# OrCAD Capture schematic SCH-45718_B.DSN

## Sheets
1 Title, ToC and Rev History: title: FRDM-XS2410EVB; rev: B; note: SCH45718 - SPF45718
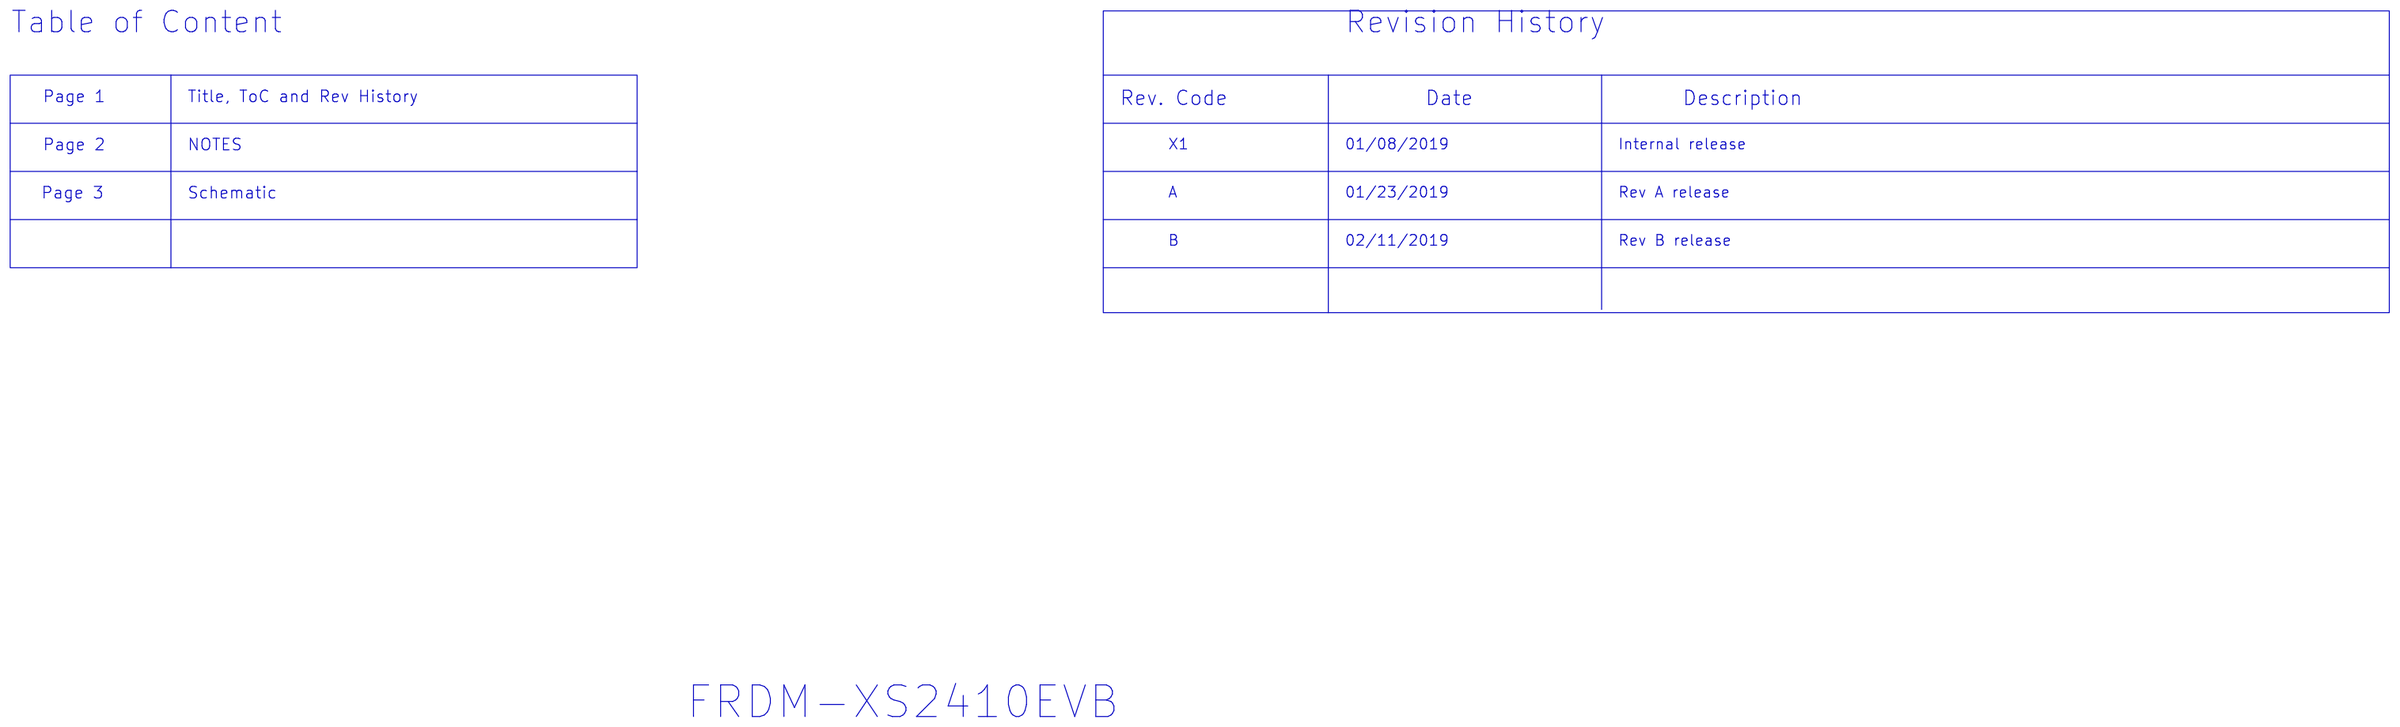
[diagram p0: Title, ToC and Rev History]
2 Notes
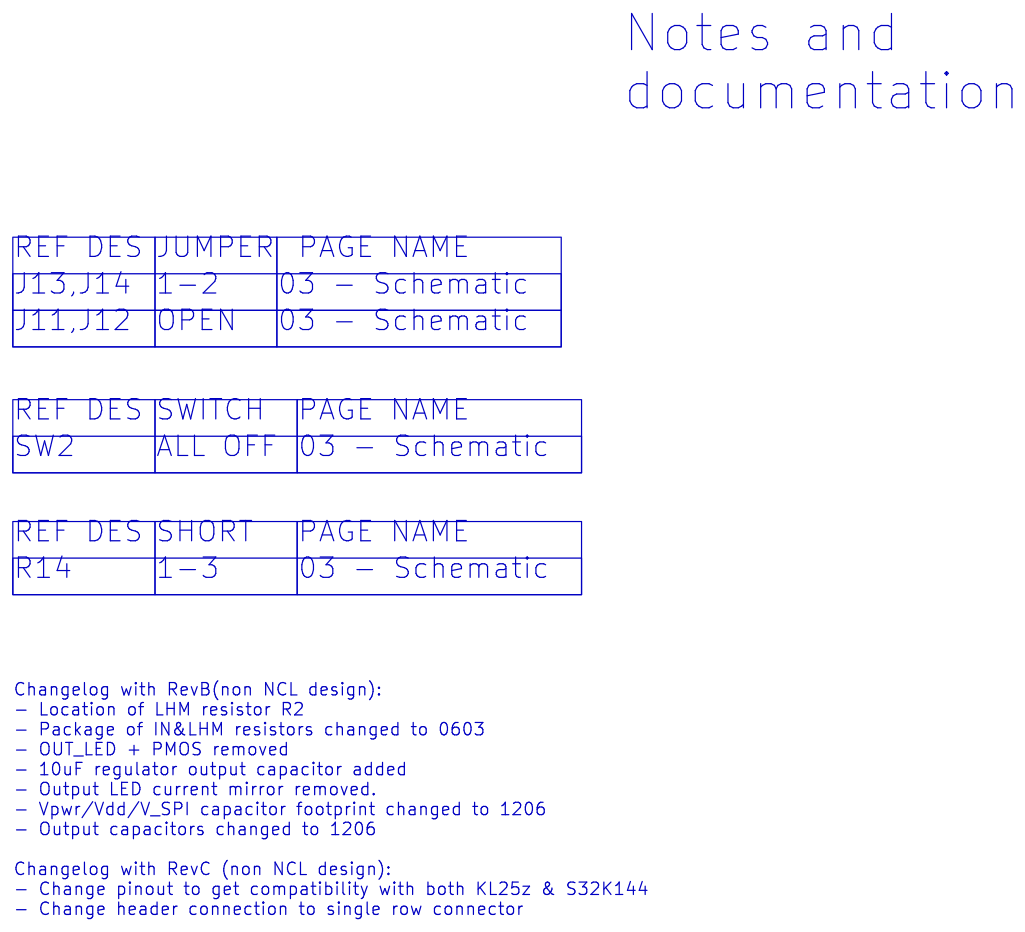
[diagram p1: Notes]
3 Schematic: size C
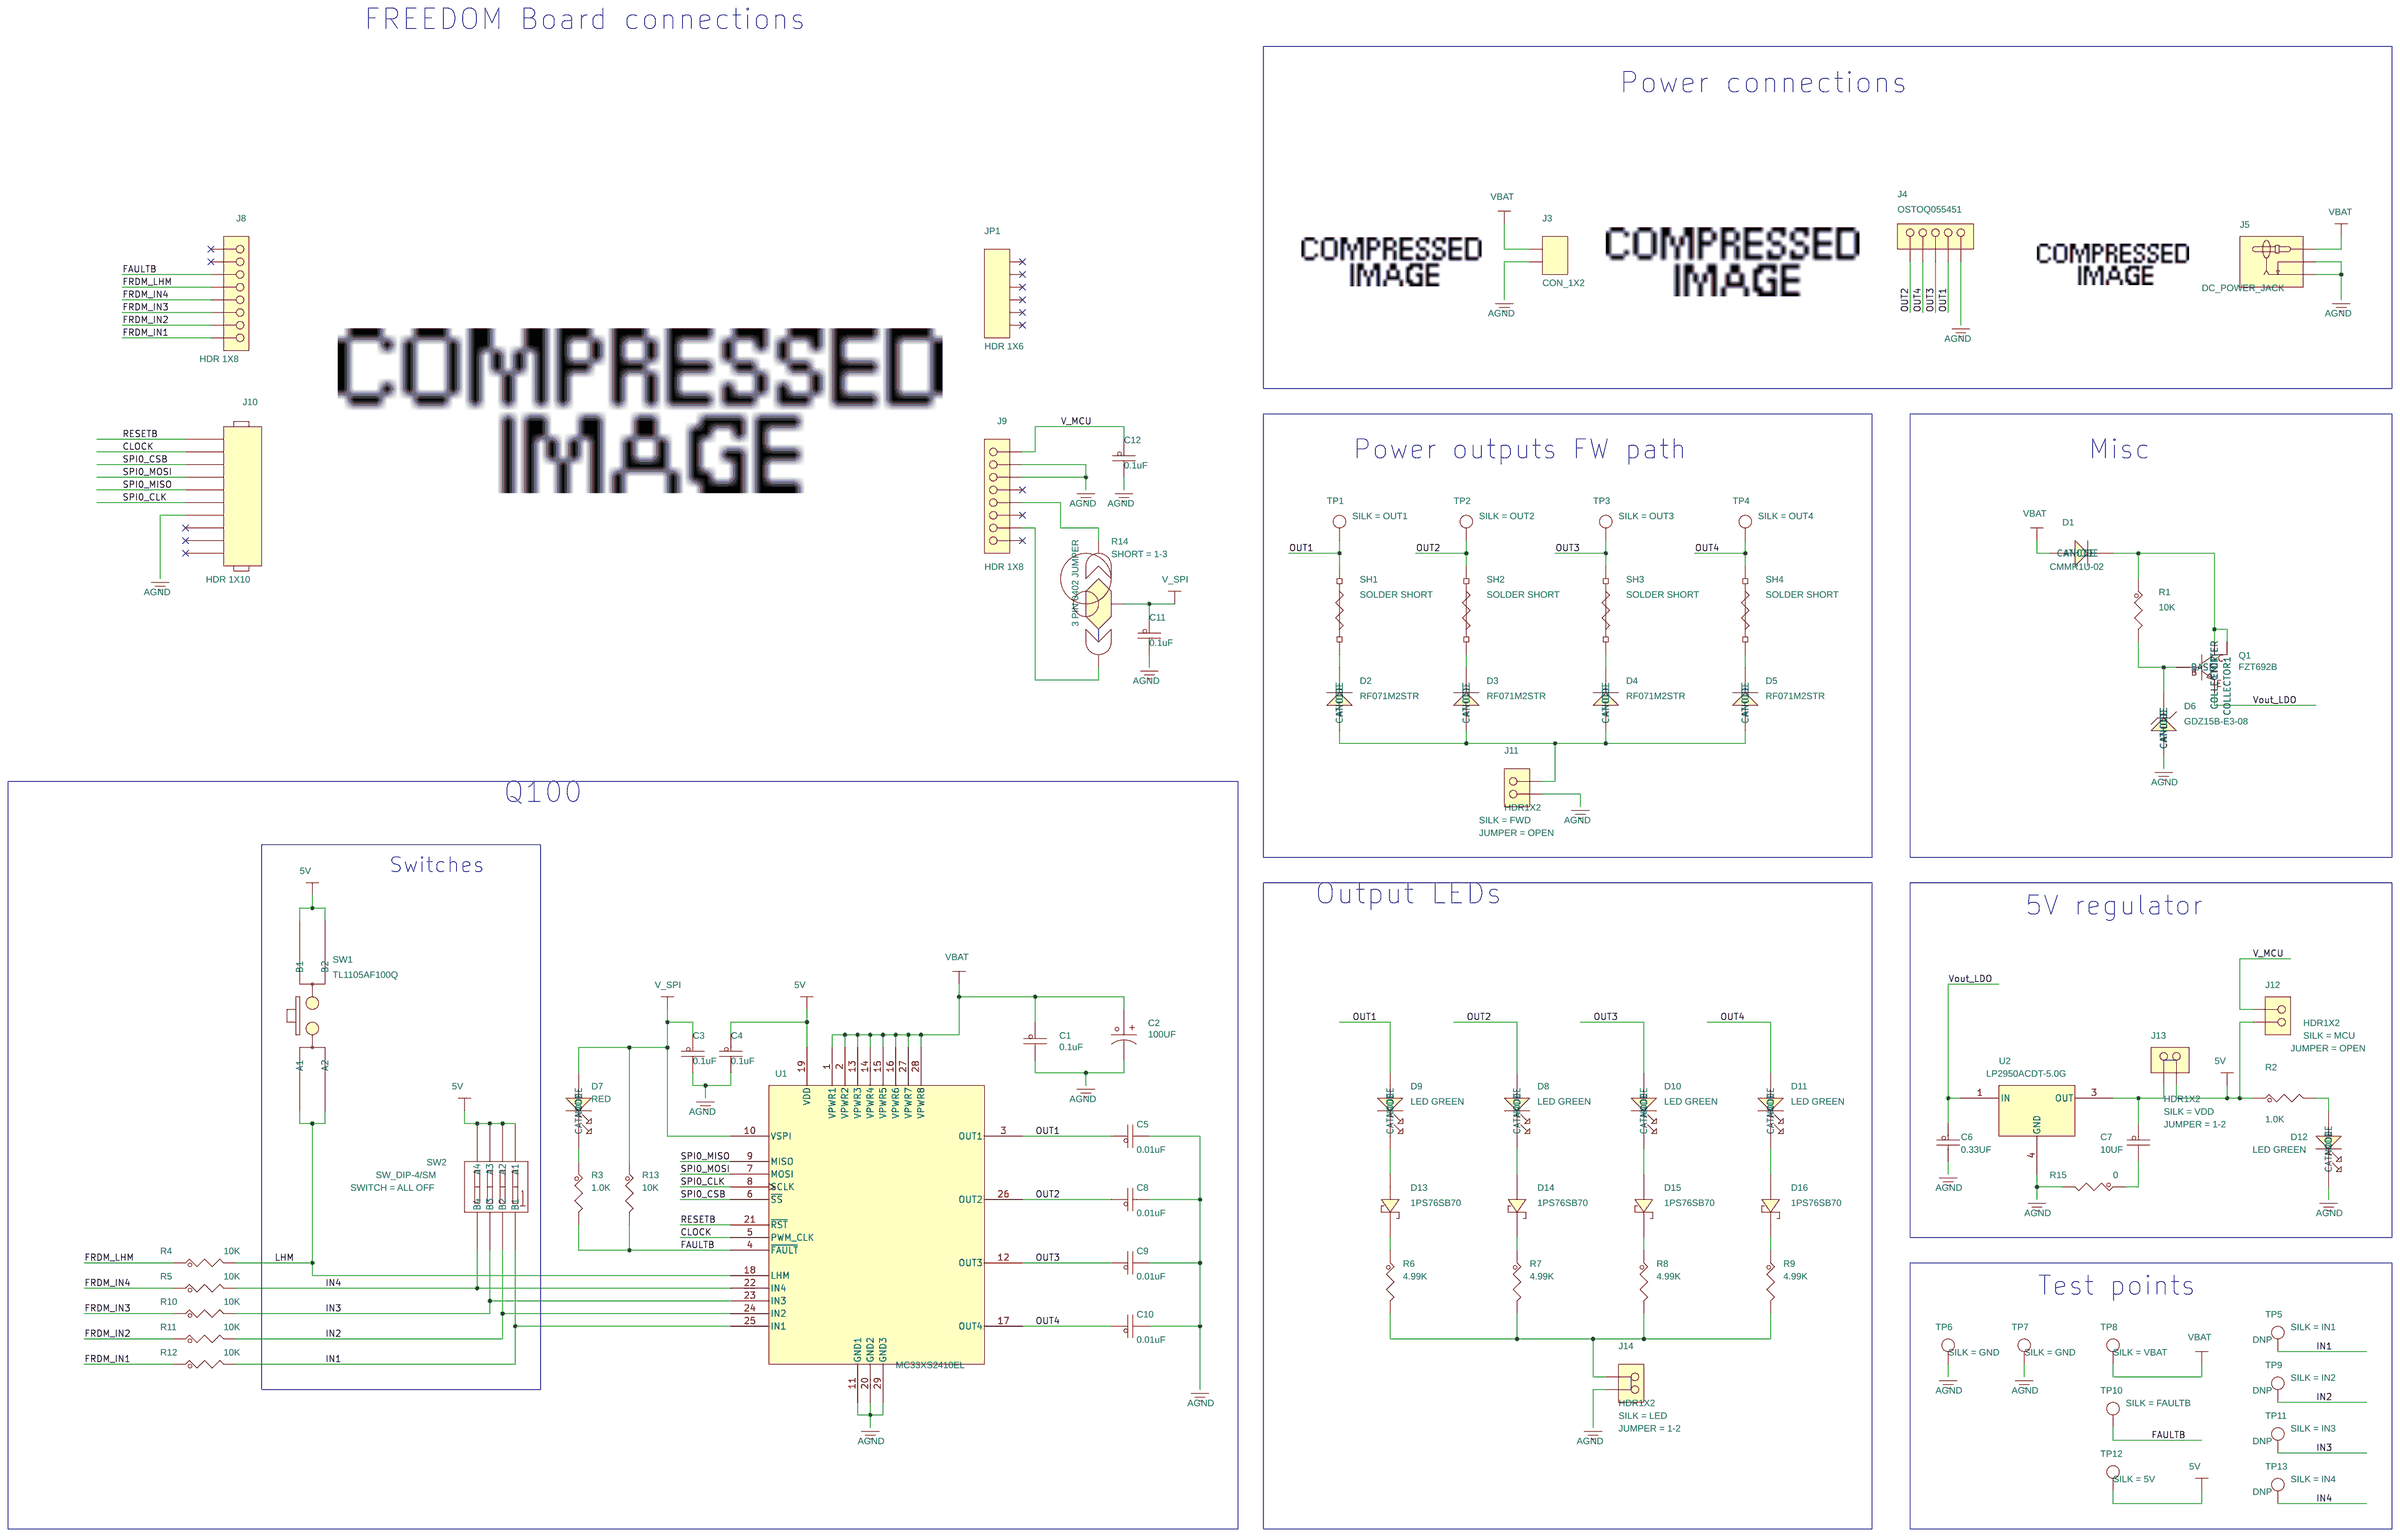
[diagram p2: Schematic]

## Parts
C1  0.1uF  [CC1206_OV]
C2  100UF  [cap_10dia_10p5]
C3  0.1uF  [CC0603_OV]
C4  0.1uF  [CC0603_OV]
C5  0.01uF  [CC0603_OV]
C6  0.33UF  [CC0603_OV]
C7  10UF  [CC0805_OV]
C8  0.01uF  [CC0603_OV]
C9  0.01uF  [CC0603_OV]
C10  0.01uF  [CC0603_OV]
C11  0.1uF  [CC0603_OV]
C12  0.1uF  [CC0603_OV]
D1  CMMR1U-02  [sod-123f]
D2  RF071M2STR  [sod123]
D3  RF071M2STR  [sod123]
D4  RF071M2STR  [sod123]
D5  RF071M2STR  [sod123]
D6  GDZ15B-E3-08  [sod323_b]
D7  RED  [LED_0603]
D8  LED GREEN  [LED_0603]
D9  LED GREEN  [LED_0603]
D10  LED GREEN  [LED_0603]
D11  LED GREEN  [LED_0603]
D12  LED GREEN  [LED_0603]
D13  1PS76SB70  [SOD323]
D14  1PS76SB70  [SOD323]
D15  1PS76SB70  [SOD323]
D16  1PS76SB70  [SOD323]
J3  CON_1X2  [con2_5p08_12p26x12_ra_th]
J4  OSTOQ055451  [con5_5p08_27p5x12_ra_th]
J5  DC_POWER_JACK  [CONN_DC_POWER_3P]
J8  HDR 1X8  [hdr1x8_2p54_th]
J9  HDR 1X8  [hdr1x8_2p54_th]
J10  HDR 1X10  [hdr_1x10_100_th]
J11  HDR1X2  [hdr1x2_5p48x2p69]
J12  HDR1X2  [hdr1x2_5p48x2p69]
J13  HDR1X2  [hdr1x2_5p48x2p69]
J14  HDR1X2  [hdr1x2_5p48x2p69]
JP1  HDR 1X6  [hdr106_b]
Q1  FZT692B  [sot223]
R1  10K  [RC0603_OV]
R2  1.0K  [RC0603_OV]
R3  1.0K  [RC0603_OV]
R4  10K  [RC0603_OV]
R5  10K  [RC0603_OV]
R6  4.99K  [RC1206_OV]
R7  4.99K  [RC1206_OV]
R8  4.99K  [RC1206_OV]
R9  4.99K  [RC1206_OV]
R10  10K  [RC0603_OV]
R11  10K  [RC0603_OV]
R12  10K  [RC0603_OV]
R13  10K  [RC0603_OV]
R14  3 PIN 0402 JUMPER  [3pin_0402_solder_blob_jumper]
R15  0  [RC0603_OV]
SH1  SOLDER SHORT  [SH0805]
SH2  SOLDER SHORT  [SH0805]
SH3  SOLDER SHORT  [SH0805]
SH4  SOLDER SHORT  [SH0805]
SW1  TL1105AF100Q  [sw4_6x6_th]
SW2  SW_DIP-4/SM  [DIP-SMT4]
TP1  TESTLOOP  [testpoint_135_070mil]
TP2  TESTLOOP  [testpoint_135_070mil]
TP3  TESTLOOP  [testpoint_135_070mil]
TP4  TESTLOOP  [testpoint_135_070mil]
TP5  TESTLOOP  [testpoint_135_070mil]
TP6  TESTLOOP  [testpoint_135_070mil]
TP7  TESTLOOP  [testpoint_135_070mil]
TP8  TESTLOOP  [testpoint_135_070mil]
TP9  TESTLOOP  [testpoint_135_070mil]
TP10  TESTLOOP  [testpoint_135_070mil]
TP11  TESTLOOP  [testpoint_135_070mil]
TP12  TESTLOOP  [testpoint_135_070mil]
TP13  TESTLOOP  [testpoint_135_070mil]
U1  MC33XS2410EL  [tssop28_tab124x222]
U2  LP2950CP  [DPAK_CASE_369C-01]

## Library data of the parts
C1 = CAP_NP: CAP CER 0.1uF 100V 20% X7R AEC-Q200 1206; AGILE_PN: 150-79769; CAD_APPROVED: Yes; FPLIST: CC1206_OV,CC1206,1206_CC; HEIGHT: 1.9 MM; MFG_NAME01: TDK; MFG_PN01: CGA5L2X7R2A104M160AE; ROHS: Yes; VOLTAGE: 100V
C2 = CAP_POL: CAP ALEL 100UF 50V 20% AEC-Q200 RADIAL SMT; AGILE_PN: 150-79346; CAD_APPROVED: Yes; HEIGHT: 12.5MM; MFG_NAME01: VISHAY INTERTECHNOLOGY; MFG_PN01: MAL214699104E3; ROHS: Yes
C3 C4 C11 C12 = CAP_NP: CAP CER 0.1uF 25V 10% X7R AEC-Q200 0603; AGILE_PN: 150-79768; CAD_APPROVED: Yes; FPLIST: CC0603_OV,CC0603,0603_CC; HEIGHT: 0.9 MM; MFG_NAME01: TDK; MFG_PN01: CGA3E2X7R1E104K080AA; ROHS: Yes
C5 C8-C10 = CAP_NP: CAP CER 0.01uF 100V 20% X7R AEC-Q200 0603; AGILE_PN: 150-79772; CAD_APPROVED: Yes; FPLIST: CC0603_OV,CC0603,0603_CC; HEIGHT: 0.8MM; MFG_NAME01: TDK; MFG_PN01: CGA3E2X7R2A103M080AA; ROHS: Yes; Tolerance: 20%; VOLTAGE: 100V
C6 = CAP_NP: CAP CER 0.33UF 50V 10% X7R 0603; AGILE_PN: 150-79257; CAD_APPROVED: Yes; FPLIST: CC0603_OV,CC0603,0603_CC; HEIGHT: 0.9MM; MFG_NAME01: TDK; MFG_PN01: C1608X7R1H334K080AC; ROHS: Yes; Tolerance: 10%; VOLTAGE: 50V
C7 = CAP_NP: CAP CER 10UF 10V 10% X7R 0805; AGILE_PN: 150-78501; CAD_APPROVED: Yes; FPLIST: CC0805_OV,CC0805,0805_CC; HEIGHT: 1.4MM; MFG_NAME01: SAMSUNG; MFG_PN01: CL21B106KPQNNNG; ROHS: Yes; Tolerance: 10%; VOLTAGE: 10V
D1 = DIODE: DIODE RECT 1A 200V SOD-123F; AGILE_PN: 480-77379; CAD_APPROVED: Yes; HEIGHT: 1.08MM; MFG_NAME01: CENTRAL SEMICONDUCTOR; MFG_PN01: CMMR1U-02 LEAD FREE; ROHS: Yes
D2-D5 = DIODE: DIODE FAST RECOVERY 0.7A 200V SOD-123; AGILE_PN: 480-78144; CAD_APPROVED: Yes; HEIGHT: 0.9MM; MFG_NAME01: ROHM; ROHS: Yes
D6 = ZDIODE: DIODE ZNR 5MA 15V 0.2W AEC-Q101 SOD-323; AGILE_PN: 480-78575; CAD_APPROVED: Yes; HEIGHT: 1.15MM; MFG_NAME01: VISHAY INTERTECHNOLOGY; ROHS: Yes
D7 = LED: LED RED SGL 1.8V 20mA 0603; AGILE_PN: 370-76737; CAD_APPROVED: Yes; HEIGHT: 0.8MM; MFG_NAME01: AVAGO TECHNOLOGIES; MFG_PN01: HSMH-C190; ROHS: Yes; Temp_Range: -40C to +85C
D8-D12 = LED: LED GRN SGL 20MA 0603; AGILE_PN: 370-76565; CAD_APPROVED: Yes; HEIGHT: 0.67MM; MFG_NAME01: osram; MFG_PN01: LG L29K-G2J1-24-Z; ROHS: Yes
D13-D16 = DIODE_SCHTKY: DIODE SCH 70mA 70V SOD323; AGILE_PN: 480-79487; CAD_APPROVED: Yes; HEIGHT: 1.1 MM; MFG_NAME01: NEXPERIA; MFG_PN01: 1PS76SB70,135; ROHS: Yes
J3 = CONN_PLUG_1X2_M: CON 1X2 PLUG RA SHRD TH 5.08MM SP 346H SN 138L; AGILE_PN: 210-80642; CAD_APPROVED: Yes; HEIGHT: 8.8MM; MFG_NAME01: ON-SHORE TECHNOLOGY; MFG_PN01: OSTOQ025451; ROHS: Yes
J4 = CONN_HDR_5X1: CON 1X5 PLUG RA SHRD TB TH 5.08MM SP 346H SN 157L; AGILE_PN: 210-81380; CAD_APPROVED: Yes; HEIGHT: 8.8MM; MFG_NAME01: ON-SHORE TECHNOLOGY; ROHS: Yes; Temp_Range: -30C to +105C
J5 = DC_POWER_JACK_3: CON 1 PWR PLUG RA TH -- 433H -- 138L; AGILE_PN: 210-30158; CAD_APPROVED: Yes; HEIGHT: 13.5 MM; MFG_NAME01: CLIFF ELECTRONIC COMPONENTS; MFG_PN01: FC68148; ROHS: Yes
J8 J9 = CONN_HDR_8X1: HDR 1X8 TH 100MIL SP 344H AU 118L; AGILE_PN: 210-80471; CAD_APPROVED: Yes; HEIGHT: 8.74MM; MFG_NAME01: WURTH ELEKTRONIK EISOS GMBH & CO. KG (ELECTRONIC & ELECTROMEHANICAL COMP); MFG_PN01: 61300811121; ROHS: Yes
J10 = HDR-1X10: HDR 1X10 TH 100MIL SP 344H AU 118L; AGILE_PN: 210-81947; CAD_APPROVED: Yes; HEIGHT: 8.74MM; MFG_NAME01: WURTH ELEKTRONIK EISOS GMBH & CO. KG (ELECTRONIC & ELECTROMEHANICAL COMP); MFG_PN01: 61301011121; ROHS: Yes; Temp_Range: -40 UP TO 105°C
J11 = CONN_HDR_2X1: HDR 1X2 TH 100MIL SP 342H AU 118L; AGILE_PN: 210-80468; CAD_APPROVED: Yes; HEIGHT: 8.69MM; JUMPER: OPEN; MFG_NAME01: WURTH ELEKTRONIK EISOS GMBH & CO. KG (ELECTRONIC & ELECTROMEHANICAL COMP); MFG_PN01: 61300211121; ROHS: Yes; SILK: FWD
J12 = CONN_HDR_2X1: HDR 1X2 TH 100MIL SP 342H AU 118L; AGILE_PN: 210-80468; CAD_APPROVED: Yes; HEIGHT: 8.69MM; JUMPER: OPEN; MFG_NAME01: WURTH ELEKTRONIK EISOS GMBH & CO. KG (ELECTRONIC & ELECTROMEHANICAL COMP); MFG_PN01: 61300211121; ROHS: Yes; SILK: MCU
J13 = CONN_HDR_2X1: HDR 1X2 TH 100MIL SP 342H AU 118L; AGILE_PN: 210-80468; CAD_APPROVED: Yes; HEIGHT: 8.69MM; JUMPER: 1-2; MFG_NAME01: WURTH ELEKTRONIK EISOS GMBH & CO. KG (ELECTRONIC & ELECTROMEHANICAL COMP); MFG_PN01: 61300211121; ROHS: Yes; SILK: VDD
J14 = CONN_HDR_2X1: HDR 1X2 TH 100MIL SP 342H AU 118L; AGILE_PN: 210-80468; CAD_APPROVED: Yes; HEIGHT: 8.69MM; JUMPER: 1-2; MFG_NAME01: WURTH ELEKTRONIK EISOS GMBH & CO. KG (ELECTRONIC & ELECTROMEHANICAL COMP); MFG_PN01: 61300211121; ROHS: Yes; SILK: LED
JP1 = CONN_PLUG_1X6_M: HDR 1X6 TH 100MIL SP 344H AU 118L; AGILE_PN: 210-80470; CAD_APPROVED: Yes; HEIGHT: 8.74MM; MFG_NAME01: WURTH ELEKTRONIK EISOS GMBH & CO. KG (ELECTRONIC & ELECTROMEHANICAL COMP); MFG_PN01: 61300611121; ROHS: Yes
Q1 = TRAN_NPN_SOT223: TRAN NPN PWR 2A 70V SOT223; AGILE_PN: 480-77898; CAD_APPROVED: Yes; HEIGHT: 1.8MM; MFG_NAME01: ZETEX INC; ROHS: Yes
R1 R4 R5 R10-R13 = RES: RES MF 10K 1/8W 1% 0603; AGILE_PN: 470-80830; CAD_APPROVED: Yes; FPLIST: RC0603_OV,RC0603,0603_CC; HEIGHT: 0.5MM; MFG_NAME01: STACKPOLE ELECTRONICS; MFG_PN01: RNCP0603FTD10K0; ROHS: Yes; Tolerance: 1%
R2 R3 = RES: RES MF 1.00K 1/10W 1% 0603; AGILE_PN: 470-75421; CAD_APPROVED: Yes; FPLIST: RC0603_OV,RC0603,0603_CC; HEIGHT: 0.55 MM; MFG_NAME01: BOURNS; MFG_PN01: CR0603-FX-1001ELF; ROHS: Yes; Tolerance: 1%
R6-R9 = RES: RES MF 4.99K 1/4W 1% 1206; AGILE_PN: 470-78673; CAD_APPROVED: Yes; FPLIST: RC1206_OV,RC1206,1206_CC; HEIGHT: 0.6MM; MFG_NAME01: VISHAY INTERTECHNOLOGY; MFG_PN01: CRCW12064K99FKEA; ROHS: Yes; Tolerance: 1%
R14 = 3_Pad_Solder_Blob_Jumper: SOLDER BLOB JUMPER 3PIN OPEN 0402 - NO PART TO ORDER; AGILE_PN: 470-81087; CAD_APPROVED: Yes; HEIGHT: 0.1016MM; MFG_NAME01: NO PART TO ORDER; MFG_PN01: N/A (CUSTOM PCB CONNECTION); ROHS: Yes; SHORT: 1-3
R15 = RES: RES MF ZERO OHM 1/10W -- 0603; AGILE_PN: 470-80866; CAD_APPROVED: Yes; FPLIST: RC0603_OV,RC0603,R603-X2,0603_CC,IND_0603HP_NSP,CC0603_OV_NSP; HEIGHT: 0.6MM; MFG_NAME01: BOURNS; MFG_PN01: CR0603J/000ELF; ROHS: Yes
SH1-SH4 = RES_SHORT-2: SOLDER SHORT 0805  SMT NO PART TO ORDER; AGILE_PN: 470-80202; CAD_APPROVED: Yes; FPLIST: SH0805,SH0805CUST,SH0805_40; HEIGHT: 0.127MM; MFG_NAME01: NOTACOMPONENT; MFG_PN01: SOLDER_SHORT_0805; ROHS: Yes
SW1 = SW_PB_ESW: SW SPST TACT NO 50mA 12V TH; AGILE_PN: 510-78260; CAD_APPROVED: Yes; HEIGHT: 5.25MM; MFG_NAME01: E SWITCH; ROHS: Yes; Temp_Range: -20C - 70C
SW2 = SW_DIP-4_SM: SW SPST DIP 0.1A@20VDC SMT; AGILE_PN: 510-77685; CAD_APPROVED: Yes; HEIGHT: 4.1MM; MFG_NAME01: CTS; MFG_PN01: 219-4MST; ROHS: Yes; SWITCH: ALL OFF
TP1 = TESTLOOP: TEST POINT PAD SIZE 3.4MM X 1.8MM SMT; AGILE_PN: 211-75906; CAD_APPROVED: Yes; FPLIST: testpoint_135_070mil,testpoint_110_045mil,testpoint_125x40milmod; HEIGHT: 1.53 MM; MFG_NAME01: KEYSTONE ELECTRONICS; MFG_PN01: 5015; ROHS: Yes; SILK: OUT1
TP2 = TESTLOOP: TEST POINT PAD SIZE 3.4MM X 1.8MM SMT; AGILE_PN: 211-75906; CAD_APPROVED: Yes; FPLIST: testpoint_135_070mil,testpoint_110_045mil,testpoint_125x40milmod; HEIGHT: 1.53 MM; MFG_NAME01: KEYSTONE ELECTRONICS; MFG_PN01: 5015; ROHS: Yes; SILK: OUT2
TP3 = TESTLOOP: TEST POINT PAD SIZE 3.4MM X 1.8MM SMT; AGILE_PN: 211-75906; CAD_APPROVED: Yes; FPLIST: testpoint_135_070mil,testpoint_110_045mil,testpoint_125x40milmod; HEIGHT: 1.53 MM; MFG_NAME01: KEYSTONE ELECTRONICS; MFG_PN01: 5015; ROHS: Yes; SILK: OUT3
TP4 = TESTLOOP: TEST POINT PAD SIZE 3.4MM X 1.8MM SMT; AGILE_PN: 211-75906; CAD_APPROVED: Yes; FPLIST: testpoint_135_070mil,testpoint_110_045mil,testpoint_125x40milmod; HEIGHT: 1.53 MM; MFG_NAME01: KEYSTONE ELECTRONICS; MFG_PN01: 5015; ROHS: Yes; SILK: OUT4
TP5 = TESTLOOP: TEST POINT PAD SIZE 3.4MM X 1.8MM SMT; AGILE_PN: 211-75906; ASSY_OPT: DNP; CAD_APPROVED: Yes; FPLIST: testpoint_135_070mil,testpoint_110_045mil,testpoint_125x40milmod; HEIGHT: 1.53 MM; MFG_NAME01: KEYSTONE ELECTRONICS; MFG_PN01: 5015; ROHS: Yes; SILK: IN1
TP6 TP7 = TESTLOOP: TEST POINT PAD SIZE 3.4MM X 1.8MM SMT; AGILE_PN: 211-75906; CAD_APPROVED: Yes; FPLIST: testpoint_135_070mil,testpoint_110_045mil,testpoint_125x40milmod; HEIGHT: 1.53 MM; MFG_NAME01: KEYSTONE ELECTRONICS; MFG_PN01: 5015; ROHS: Yes; SILK: GND
TP8 = TESTLOOP: TEST POINT PAD SIZE 3.4MM X 1.8MM SMT; AGILE_PN: 211-75906; CAD_APPROVED: Yes; FPLIST: testpoint_135_070mil,testpoint_110_045mil,testpoint_125x40milmod; HEIGHT: 1.53 MM; MFG_NAME01: KEYSTONE ELECTRONICS; MFG_PN01: 5015; ROHS: Yes; SILK: VBAT
TP9 = TESTLOOP: TEST POINT PAD SIZE 3.4MM X 1.8MM SMT; AGILE_PN: 211-75906; ASSY_OPT: DNP; CAD_APPROVED: Yes; FPLIST: testpoint_135_070mil,testpoint_110_045mil,testpoint_125x40milmod; HEIGHT: 1.53 MM; MFG_NAME01: KEYSTONE ELECTRONICS; MFG_PN01: 5015; ROHS: Yes; SILK: IN2
TP10 = TESTLOOP: TEST POINT PAD SIZE 3.4MM X 1.8MM SMT; AGILE_PN: 211-75906; CAD_APPROVED: Yes; FPLIST: testpoint_135_070mil,testpoint_110_045mil,testpoint_125x40milmod; HEIGHT: 1.53 MM; MFG_NAME01: KEYSTONE ELECTRONICS; MFG_PN01: 5015; ROHS: Yes; SILK: FAULTB
TP11 = TESTLOOP: TEST POINT PAD SIZE 3.4MM X 1.8MM SMT; AGILE_PN: 211-75906; ASSY_OPT: DNP; CAD_APPROVED: Yes; FPLIST: testpoint_135_070mil,testpoint_110_045mil,testpoint_125x40milmod; HEIGHT: 1.53 MM; MFG_NAME01: KEYSTONE ELECTRONICS; MFG_PN01: 5015; ROHS: Yes; SILK: IN3
TP12 = TESTLOOP: TEST POINT PAD SIZE 3.4MM X 1.8MM SMT; AGILE_PN: 211-75906; CAD_APPROVED: Yes; FPLIST: testpoint_135_070mil,testpoint_110_045mil,testpoint_125x40milmod; HEIGHT: 1.53 MM; MFG_NAME01: KEYSTONE ELECTRONICS; MFG_PN01: 5015; ROHS: Yes; SILK: 5V
TP13 = TESTLOOP: TEST POINT PAD SIZE 3.4MM X 1.8MM SMT; AGILE_PN: 211-75906; ASSY_OPT: DNP; CAD_APPROVED: Yes; FPLIST: testpoint_135_070mil,testpoint_110_045mil,testpoint_125x40milmod; HEIGHT: 1.53 MM; MFG_NAME01: KEYSTONE ELECTRONICS; MFG_PN01: 5015; ROHS: Yes; SILK: IN4
U1 = MC33XS4210_28P: IC QUAD HS SW 100mOhm 3-60V HTSSOP28; AGILE_PN: TMP-WF-29908; CAD_APPROVED: Yes; HEIGHT: 1.1MM; MFG_NAME01: NXP SEMICONDUCTORS; PRE_APN: 315-81400; ROHS: Yes
U2 = MC7805: IC VREG LDO 5V 100MA 30V DPAK; AGILE_PN: 312-78250; CAD_APPROVED: Yes; HEIGHT: 2.38MM; MFG_NAME01: On Semiconductor; MFG_PN01: LP2950ACDT-5.0G; ROHS: Yes

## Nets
5V: C4.1 J12.2 J13.2 R2.1 SW1.3(B1) SW1.4(B2) SW2.1(A1) SW2.2(A2) SW2.3(A3) SW2.4(A4) TP12.1(Pin1) U1.19(VDD)
AGND: C1.2 C2.2 C3.2 C4.2 C5.2 C6.2 C8.2 C9.2 C10.2 C11.2 C12.2 D6.A(ANODE) D12.C(CATHODE) J3.2 J4.5 J5.2 J5.3 J9.2 J9.3 J10.7 J11.1 J14.2 R15.2 TP6.1(Pin1) TP7.1(Pin1) U1.11(GND1) U1.20(GND2) U1.29(GND3) U2.4(GND)
VBAT: C1.1 C2.1 D1.A(ANODE) J3.1 J5.1 TP8.1(Pin1) U1.1(VPWR1) U1.2(VPWR2) U1.13(VPWR3) U1.14(VPWR4) U1.15(VPWR5) U1.16(VPWR6) U1.27(VPWR7) U1.28(VPWR8)
CLOCK: J10.2 U1.5(PWM_CLK)
FAULTB: J8.3 R3.2 R13.2 TP10.1(Pin1) U1.4(~{FAULT})
FRDM_IN1: J8.8 R12.1
FRDM_IN2: J8.7 R11.1
FRDM_IN3: J8.6 R10.1
FRDM_IN4: J8.5 R5.1
FRDM_LHM: J8.4 R4.1
IN1: R12.2 SW2.8(B1) TP5.1(Pin1) U1.25(IN1)
IN2: R11.2 SW2.7(B2) TP9.1(Pin1) U1.24(IN2)
IN3: R10.2 SW2.6(B3) TP11.1(Pin1) U1.23(IN3)
IN4: R5.2 SW2.5(B4) TP13.1(Pin1) U1.22(IN4)
LHM: R4.2 SW1.1(A1) SW1.2(A2) U1.18(LHM)
OUT1: C5.1 D9.A(ANODE) J4.4 SH1.1 TP1.1(Pin1) U1.3(OUT1)
OUT2: C8.1 D8.A(ANODE) J4.1 SH2.1 TP2.1(Pin1) U1.26(OUT2)
OUT3: C9.1 D10.A(ANODE) J4.3 SH3.1 TP3.1(Pin1) U1.12(OUT3)
OUT4: C10.1 D11.A(ANODE) J4.2 SH4.1 TP4.1(Pin1) U1.17(OUT4)
RESETB: J10.1 U1.21(~{RST})
SPI0_CLK: J10.6 U1.8(SCLK)
SPI0_CSB: J10.3 U1.6(~{SS})
SPI0_MISO: J10.5 U1.9(MISO)
SPI0_MOSI: J10.4 U1.7(MOSI)
V_MCU: C12.1 J9.1 J12.1
V_SPI: C3.1 C11.1 D7.A(ANODE) R13.1 R14.1 U1.10(VSPI)
Vout_LDO: C6.1 Q1.3(EMITTER) U2.1(IN)
N18288430: J9.5 R14.2
N18288522: D1.C(CATHODE) Q1.2(COLLECTOR) Q1.4(COLLECTOR1) R1.1
N18288583: D6.C(CATHODE) Q1.1(BASE) R1.2
N18288585: D2.C(CATHODE) SH1.2
N18288587: D3.C(CATHODE) SH2.2
N18288662: D2.A(ANODE) D3.A(ANODE) D4.A(ANODE) D5.A(ANODE) J11.2
N18289047: C7.1 J13.1 U2.3(OUT)
N18289088: D12.A(ANODE) R2.2
N18289158: D9.C(CATHODE) D13.A
N18289160: D8.C(CATHODE) D14.A
N18289162: D10.C(CATHODE) D15.A
N18289164: D11.C(CATHODE) D16.A
N18289215: C7.2 R15.1
N18289308: D13.C R6.1
N18289310: D14.C R7.1
N18289312: D15.C R8.1
N18289314: D16.C R9.1
N18289449: J14.1 R6.2 R7.2 R8.2 R9.2
N18304925: D7.C(CATHODE) R3.1
N18308854: J9.7 R14.3
N18313687: D4.C(CATHODE) SH3.2
N18313700: D5.C(CATHODE) SH4.2

Not connected (* = marked no-connect by the designer): J8 1* 2*; J9 4* 6* 8*; J10 8* 9* 10*; JP1 1* 2* 3* 4* 5* 6*

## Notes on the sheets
sheet 1
- Table of Content
- Revision History
- Page 1
- Title, ToC and Rev History
- Rev. Code
- Date
- Description
- Page 2
- NOTES
- X1
- 01/08/2019
- Internal release
- Page 3
- Schematic
- A
- 01/23/2019
- Rev A release
- B
- 02/11/2019
- Rev B release
- FRDM-XS2410EVB
sheet 2
- Notes and
  documentation
- REF DES
- JUMPER
- PAGE NAME
- J13,J14
- 1-2
- 03 - Schematic
- J11,J12
- OPEN
- 03 - Schematic
- REF DES
- SWITCH
- PAGE NAME
- SW2
- ALL OFF
- 03 - Schematic
- REF DES
- SHORT
- PAGE NAME
- R14
- 1-3
- 03 - Schematic
- Changelog with RevB(non NCL design):
  - Location of LHM resistor R2
  - Package of IN&LHM resistors changed to 0603
  - OUT_LED + PMOS removed
  - 10uF regulator output capacitor added
  - Output LED current mirror removed.
  - Vpwr/Vdd/V_SPI capacitor footprint changed to 1206
  - Output capacitors changed to 1206
  Changelog with RevC (non NCL design):
  - Change pinout to get compatibility with both KL25z & S32K144
  - Change header connection to single row connector
sheet 3
- FREEDOM Board connections
- Power connections
- Power outputs FW path
- Misc
- Q100
- Switches
- Output LEDs
- 5V regulator
- Test points
